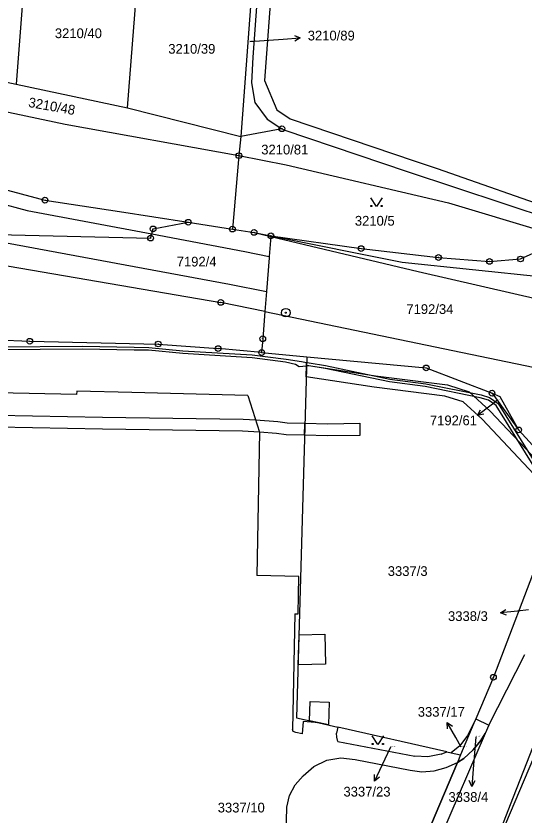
# Model space of a CAD drawing. Extents: x -593183 to -588034, y -1130415 to -1124994.
# Drawn here: x -592233 to -592144.3, y -1128273.9 to -1128134.3 of the extents above; entities that cross this region are included whole.
import ezdxf

# ---------------------------------------------------------------- set-up
doc = ezdxf.new("R2010")
doc.units = 0
for name, color, linetype in [('Vrstva 1', 7, 'Continuous'), ('Vrstva 16', 7, 'Continuous'), ('Vrstva 18', 7, 'Continuous'), ('Vrstva 24', 7, 'Continuous'), ('Vrstva 25', 7, 'Continuous'), ('Vrstva 27', 7, 'Continuous'), ('Vrstva 4', 7, 'Continuous')]:
    doc.layers.add(name, color=color, linetype=linetype)

msp = doc.modelspace()

# ---------------------------------------------------------------- linework, layer by layer
at = {"layer": 'Vrstva 1'}
for p, q in [((-592188.99, -1128105.22), (-592191.64, -1128141.44)), ((-592231.43, -1128125.97), (-592232.96, -1128146.18)), ((-592213.52, -1128150.28), (-592211.75, -1128127.62)), ((-592191.84, -1128129.32), (-592193.74, -1128155.31)), ((-592252.68, -1128142.07), (-592232.96, -1128146.18)), ((-592191.64, -1128141.44), (-592191.87, -1128145.92)), ((-592232.96, -1128146.18), (-592213.52, -1128150.28)), ((-592191.87, -1128145.92), (-592191.31, -1128149.37)), ((-592248.8, -1128148.01), (-592224.41, -1128153.13)), ((-592191.31, -1128149.37), (-592189.17, -1128152.26)), ((-592213.52, -1128150.28), (-592193.74, -1128155.31)), ((-592189.17, -1128152.26), (-592186.58, -1128153.95)), ((-592224.41, -1128153.13), (-592194.09, -1128158.65)), ((-592193.74, -1128155.31), (-592194.09, -1128158.65)), ((-592186.58, -1128153.95), (-592193.74, -1128155.31)), ((-592194.09, -1128158.65), (-592195.22, -1128171.47)), ((-592194.09, -1128158.65), (-592185.82, -1128160.27)), ((-592252.86, -1128159.79), (-592227.94, -1128166.42)), ((-592185.82, -1128160.27), (-592157.53, -1128166.89)), ((-592227.94, -1128166.42), (-592214.96, -1128168.42)), ((-592157.53, -1128166.89), (-592136.91, -1128173.09)), ((-592214.96, -1128168.42), (-592202.93, -1128170.28)), ((-592209.07, -1128171.45), (-592202.93, -1128170.28)), ((-592202.93, -1128170.28), (-592195.22, -1128171.47)), ((-592209.31, -1128172.32), (-592209.07, -1128171.45)), ((-592195.22, -1128171.47), (-592191.45, -1128172.05)), ((-592191.45, -1128172.05), (-592188.52, -1128172.64)), ((-592191.45, -1128172.05), (-592188.53, -1128172.75)), ((-592242.75, -1128172.26), (-592209.5, -1128173.04)), ((-592209.5, -1128173.04), (-592209.31, -1128172.32)), ((-592188.53, -1128172.75), (-592188.8, -1128176.25)), ((-592188.53, -1128172.75), (-592162.78, -1128178.89)), ((-592188.52, -1128172.64), (-592172.74, -1128174.88)), ((-592188.52, -1128172.64), (-592165.62, -1128177.22)), ((-592144.94, -1128176.69), (-592137.52, -1128173.33)), ((-592244.7, -1128176.17), (-592197.26, -1128184.27)), ((-592188.8, -1128176.25), (-592188.82, -1128176.49)), ((-592172.74, -1128174.88), (-592159.25, -1128176.43)), ((-592188.82, -1128176.49), (-592189.28, -1128182.39)), ((-592165.62, -1128177.22), (-592139.54, -1128179.94)), ((-592159.25, -1128176.43), (-592150.34, -1128177.12)), ((-592150.34, -1128177.12), (-592144.94, -1128176.69)), ((-592162.78, -1128178.89), (-592136.37, -1128184.95)), ((-592189.28, -1128182.39), (-592189.56, -1128185.87)), ((-592189.56, -1128185.87), (-592197.26, -1128184.27)), ((-592189.56, -1128185.87), (-592189.93, -1128190.61)), ((-592189.56, -1128185.87), (-592140.83, -1128195.96)), ((-592248.77, -1128190.28), (-592230.6, -1128191.05)), ((-592230.6, -1128191.05), (-592208.18, -1128191.53)), ((-592208.18, -1128191.53), (-592197.71, -1128192.32)), ((-592189.93, -1128190.61), (-592190.12, -1128193.03)), ((-592190.12, -1128193.03), (-592197.71, -1128192.32)), ((-592190.12, -1128193.03), (-592182.24, -1128193.77)), ((-592182.24, -1128193.77), (-592161.4, -1128195.71)), ((-592161.4, -1128195.71), (-592149.91, -1128200.11)), ((-592222.43, -1128200.36), (-592243.96, -1128199.91)), ((-592222.41, -1128199.76), (-592222.43, -1128200.36)), ((-592212.8, -1128200), (-592222.41, -1128199.76)), ((-592192.51, -1128200.51), (-592212.8, -1128200)), ((-592192.51, -1128200.51), (-592190.47, -1128206.93)), ((-592149.91, -1128200.11), (-592145.26, -1128206.52)), ((-592149.91, -1128200.11), (-592148.54, -1128200.68)), ((-592148.54, -1128200.68), (-592145.26, -1128206.52)), ((-592190.47, -1128206.93), (-592190.98, -1128231.93)), ((-592141.59, -1128210.59), (-592145.26, -1128206.52)), ((-592141.47, -1128228.18), (-592149.67, -1128249.69)), ((-592183.64, -1128232.11), (-592190.98, -1128231.93)), ((-592183.77, -1128238.65), (-592183.64, -1128232.11)), ((-592184.31, -1128238.64), (-592184.76, -1128258.83)), ((-592184.31, -1128238.64), (-592183.77, -1128238.65)), ((-592150.49, -1128258.09), (-592144.18, -1128245.72)), ((-592149.67, -1128249.69), (-592152.74, -1128256.96)), ((-592137.9, -1128249.31), (-592146.23, -1128270.62)), ((-592138.74, -1128254.44), (-592152.18, -1128286.25)), ((-592152.74, -1128256.96), (-592153.06, -1128257.71)), ((-592152.74, -1128256.96), (-592150.49, -1128258.09)), ((-592182.89, -1128257.44), (-592183.03, -1128259.56)), ((-592180.09, -1128257.67), (-592182.89, -1128257.44)), ((-592180.09, -1128257.67), (-592176.84, -1128258.4)), ((-592176.84, -1128258.4), (-592177.06, -1128259.46)), ((-592157.78, -1128262.71), (-592176.84, -1128258.4)), ((-592153.06, -1128257.71), (-592155.4, -1128263.25)), ((-592153.06, -1128257.71), (-592154.18, -1128259.89)), ((-592150.49, -1128258.09), (-592151.1, -1128259.5)), ((-592184.6, -1128259.17), (-592184.76, -1128258.83)), ((-592184.18, -1128259.34), (-592184.6, -1128259.17)), ((-592183.03, -1128259.56), (-592184.18, -1128259.34)), ((-592177, -1128260.16), (-592177.06, -1128259.46)), ((-592154.18, -1128259.89), (-592155.51, -1128261.69)), ((-592151.1, -1128259.5), (-592151.87, -1128260.74)), ((-592176.8, -1128260.91), (-592177, -1128260.16)), ((-592176.8, -1128260.91), (-592163.38, -1128263.5)), ((-592151.87, -1128260.74), (-592153.2, -1128262.38)), ((-592158.79, -1128263.12), (-592157.78, -1128262.71)), ((-592157.78, -1128262.71), (-592157.05, -1128262.88)), ((-592155.51, -1128261.69), (-592157.05, -1128262.88)), ((-592153.2, -1128262.38), (-592154.84, -1128263.86)), ((-592161.11, -1128263.6), (-592163.38, -1128263.5)), ((-592158.79, -1128263.12), (-592161.11, -1128263.6)), ((-592157.05, -1128262.88), (-592155.4, -1128263.25)), ((-592155.4, -1128263.25), (-592155.96, -1128264.56)), ((-592154.84, -1128263.86), (-592155.96, -1128264.56)), ((-592155.96, -1128264.56), (-592162.65, -1128280.4)), ((-592146.23, -1128270.62), (-592151.24, -1128283.43))]:
    msp.add_line(p, q, dxfattribs=at)
for points in [[(-592185.6, -1128090.36), (-592186.91, -1128108.64), (-592189.62, -1128145.54), (-592187.45, -1128150.66), (-592185.13, -1128152.24), (-592163.48, -1128159.55), (-592159.51, -1128160.9), (-592137.89, -1128168.47)], [(-592139.33, -1128169.87), (-592164.69, -1128161.47), (-592186.2, -1128154.2), (-592186.58, -1128153.95)], [(-592182.24, -1128193.77), (-592184.01, -1128256.78), (-592180.09, -1128257.67)]]:
    msp.add_lwpolyline(points, dxfattribs=at)
at = {"layer": 'Vrstva 16'}
for p, q in [((-592192.21, -1128138.72), (-592186.36, -1128138.3)), ((-592148.93, -1128201.32), (-592150.05, -1128202.18)), ((-592143.53, -1128237.93), (-592145.45, -1128238.14)), ((-592155.28, -1128261.88), (-592156.23, -1128260.21)), ((-592152.74, -1128260.07), (-592153.21, -1128265.75)), ((-592167.65, -1128261.88), (-592169.14, -1128265.09))]:
    msp.add_line(p, q, dxfattribs=at)
at = {"layer": 'Vrstva 24'}
for centre, radius in [((-592186.58, -1128153.95), 0.5), ((-592186.58, -1128153.95), 0.0327), ((-592194.09, -1128158.65), 0.5), ((-592194.09, -1128158.65), 0.0327), ((-592227.94, -1128166.42), 0.5), ((-592227.94, -1128166.42), 0.0327), ((-592202.93, -1128170.28), 0.5), ((-592202.93, -1128170.28), 0.0327), ((-592209.07, -1128171.45), 0.5), ((-592209.07, -1128171.45), 0.0327), ((-592195.22, -1128171.47), 0.5), ((-592195.22, -1128171.47), 0.0327), ((-592191.45, -1128172.05), 0.5), ((-592191.45, -1128172.05), 0.0327), ((-592209.5, -1128173.04), 0.5), ((-592209.5, -1128173.04), 0.0327), ((-592188.52, -1128172.64), 0.5), ((-592188.52, -1128172.64), 0.0327), ((-592172.74, -1128174.88), 0.5), ((-592172.74, -1128174.88), 0.0327), ((-592159.25, -1128176.43), 0.5), ((-592144.94, -1128176.69), 0.5), ((-592159.25, -1128176.43), 0.0327), ((-592150.34, -1128177.12), 0.5), ((-592150.34, -1128177.12), 0.0327), ((-592144.94, -1128176.69), 0.0327), ((-592197.26, -1128184.27), 0.5), ((-592197.26, -1128184.27), 0.0327), ((-592185.92, -1128186.06), 0.75), ((-592185.92, -1128186.06), 0.0903), ((-592189.93, -1128190.61), 0.5), ((-592230.6, -1128191.05), 0.5), ((-592230.6, -1128191.05), 0.0327), ((-592208.18, -1128191.53), 0.5), ((-592208.18, -1128191.53), 0.0327), ((-592189.93, -1128190.61), 0.0327), ((-592197.71, -1128192.32), 0.5), ((-592197.71, -1128192.32), 0.0327), ((-592190.12, -1128193.03), 0.5), ((-592190.12, -1128193.03), 0.0327), ((-592161.4, -1128195.71), 0.5), ((-592161.4, -1128195.71), 0.0327), ((-592149.91, -1128200.11), 0.5), ((-592149.91, -1128200.11), 0.0327), ((-592145.26, -1128206.52), 0.5), ((-592145.26, -1128206.52), 0.0327), ((-592149.67, -1128249.69), 0.5), ((-592149.67, -1128249.69), 0.0327)]:
    msp.add_circle(centre, radius, dxfattribs=at)
at = {"layer": 'Vrstva 25'}
for p, q in [((-592186.36, -1128138.3), (-592183.37, -1128138.08)), ((-592150.05, -1128202.18), (-592152.43, -1128204.01)), ((-592145.45, -1128238.14), (-592148.43, -1128238.47)), ((-592156.23, -1128260.21), (-592157.71, -1128257.6)), ((-592169.14, -1128265.09), (-592170.4, -1128267.81)), ((-592153.21, -1128265.75), (-592153.46, -1128268.74))]:
    msp.add_line(p, q, dxfattribs=at)
for points in [[(-592184.4, -1128137.66), (-592183.37, -1128138.08), (-592184.33, -1128138.65)], [(-592169.08, -1128166.03), (-592170.08, -1128167.53), (-592171.08, -1128166.03)], [(-592151.33, -1128203.8), (-592152.43, -1128204.01), (-592151.94, -1128203)], [(-592147.38, -1128238.85), (-592148.43, -1128238.47), (-592147.49, -1128237.86)], [(-592157.65, -1128258.72), (-592157.71, -1128257.6), (-592156.78, -1128258.22)], [(-592168.85, -1128259.95), (-592169.85, -1128261.45), (-592170.85, -1128259.95)], [(-592169.53, -1128267.11), (-592170.4, -1128267.81), (-592170.43, -1128266.69)], [(-592152.88, -1128267.78), (-592153.46, -1128268.74), (-592153.87, -1128267.7)]]:
    msp.add_lwpolyline(points, dxfattribs=at)
for centre in [(-592170.98, -1128167.43), (-592169.18, -1128167.43), (-592170.75, -1128261.35), (-592168.95, -1128261.35)]:
    msp.add_circle(centre, 0.1, dxfattribs=at)
at = {"layer": 'Vrstva 27'}
for p, q in [((-592246.64, -1128192.12), (-592221.4, -1128191.93)), ((-592221.4, -1128192.43), (-592246.62, -1128192.62)), ((-592221.4, -1128191.93), (-592212.36, -1128192.09)), ((-592212.38, -1128192.59), (-592221.4, -1128192.43)), ((-592209.87, -1128192.63), (-592212.38, -1128192.59)), ((-592212.36, -1128192.09), (-592209.83, -1128192.13)), ((-592203.89, -1128193.2), (-592209.87, -1128192.63)), ((-592209.83, -1128192.13), (-592203.87, -1128192.7)), ((-592203.87, -1128192.7), (-592191.75, -1128193.44)), ((-592191.79, -1128193.94), (-592203.89, -1128193.2)), ((-592185.97, -1128194.69), (-592191.79, -1128193.94)), ((-592191.75, -1128193.44), (-592185.85, -1128194.2)), ((-592185.85, -1128194.2), (-592183.16, -1128194.56)), ((-592184.19, -1128195.12), (-592185.97, -1128194.69)), ((-592183.6, -1128195.53), (-592184.19, -1128195.12)), ((-592182.29, -1128195.38), (-592183.6, -1128195.53)), ((-592183.16, -1128194.56), (-592182.27, -1128194.75)), ((-592182.34, -1128197.27), (-592182.28, -1128195.25)), ((-592182.29, -1128195.38), (-592182.27, -1128194.75)), ((-592182.27, -1128194.75), (-592182.29, -1128195.38)), ((-592181.91, -1128195.33), (-592182.29, -1128195.38)), ((-592182.28, -1128195.25), (-592170.22, -1128197.07)), ((-592182.27, -1128194.75), (-592181.85, -1128194.84)), ((-592179.05, -1128195.79), (-592181.91, -1128195.33)), ((-592181.85, -1128194.84), (-592178.95, -1128195.3)), ((-592167.82, -1128198.15), (-592179.05, -1128195.79)), ((-592178.95, -1128195.3), (-592167.73, -1128197.65)), ((-592170.22, -1128197.07), (-592157.68, -1128198.66)), ((-592170.5, -1128199.05), (-592182.34, -1128197.27)), ((-592161.55, -1128198.97), (-592167.82, -1128198.15)), ((-592167.73, -1128197.65), (-592161.47, -1128198.47)), ((-592161.47, -1128198.47), (-592151.81, -1128200.43)), ((-592158.12, -1128200.62), (-592170.5, -1128199.05)), ((-592151.95, -1128200.91), (-592161.55, -1128198.97)), ((-592157.68, -1128198.66), (-592153.91, -1128199.86)), ((-592153.91, -1128199.86), (-592150.22, -1128203.23)), ((-592154.93, -1128201.64), (-592158.12, -1128200.62)), ((-592150.55, -1128201.35), (-592151.95, -1128200.91)), ((-592151.81, -1128200.43), (-592150.33, -1128200.89)), ((-592149.19, -1128202.29), (-592150.55, -1128201.35)), ((-592150.33, -1128200.89), (-592148.83, -1128201.93)), ((-592151.62, -1128204.65), (-592154.93, -1128201.64)), ((-592142.25, -1128213.44), (-592149.19, -1128202.29)), ((-592148.83, -1128201.93), (-592142.15, -1128212.67)), ((-592242.3, -1128203.8), (-592217.88, -1128204.3)), ((-592150.22, -1128203.23), (-592140.42, -1128213.65)), ((-592217.88, -1128204.3), (-592193.37, -1128204.62)), ((-592193.37, -1128204.62), (-592191.16, -1128204.77)), ((-592191.16, -1128204.77), (-592187.28, -1128205.04)), ((-592187.28, -1128205.04), (-592185.67, -1128205.26)), ((-592185.67, -1128205.26), (-592182.56, -1128205.34)), ((-592182.56, -1128205.34), (-592182.62, -1128207.44)), ((-592182.62, -1128207.44), (-592182.56, -1128205.34)), ((-592182.56, -1128205.34), (-592178.58, -1128205.44)), ((-592178.58, -1128205.44), (-592173, -1128205.37)), ((-592173, -1128205.37), (-592172.97, -1128207.48)), ((-592142.62, -1128214.23), (-592151.62, -1128204.65)), ((-592217.92, -1128206.41), (-592242.34, -1128205.91)), ((-592193.45, -1128206.73), (-592217.92, -1128206.41)), ((-592190.47, -1128206.93), (-592193.45, -1128206.73)), ((-592187.5, -1128207.14), (-592190.47, -1128206.93)), ((-592185.83, -1128207.36), (-592187.5, -1128207.14)), ((-592182.62, -1128207.44), (-592185.83, -1128207.36)), ((-592178.6, -1128207.55), (-592182.62, -1128207.44)), ((-592172.97, -1128207.48), (-592178.6, -1128207.55)), ((-592183.75, -1128247.53), (-592183.6, -1128242.27)), ((-592183.6, -1128242.27), (-592179.08, -1128242.16)), ((-592179.08, -1128242.16), (-592178.95, -1128247.41)), ((-592178.95, -1128247.41), (-592183.75, -1128247.53)), ((-592181.75, -1128257.29), (-592181.63, -1128253.94)), ((-592181.63, -1128253.94), (-592178.33, -1128254.06)), ((-592178.33, -1128254.06), (-592178.48, -1128258.03)), ((-592180.09, -1128257.67), (-592181.75, -1128257.29)), ((-592178.48, -1128258.03), (-592180.09, -1128257.67)), ((-592151.1, -1128259.5), (-592162.55, -1128286.12)), ((-592151.87, -1128260.74), (-592151.1, -1128259.5)), ((-592153.2, -1128262.38), (-592151.87, -1128260.74)), ((-592154.84, -1128263.86), (-592153.2, -1128262.38)), ((-592180.99, -1128265.26), (-592178.73, -1128264.19)), ((-592178.73, -1128264.19), (-592176.27, -1128263.76)), ((-592176.27, -1128263.76), (-592173.79, -1128264.08)), ((-592173.79, -1128264.08), (-592164.17, -1128265.91)), ((-592155.96, -1128264.56), (-592154.84, -1128263.86)), ((-592182.85, -1128266.88), (-592180.99, -1128265.26)), ((-592155.96, -1128264.56), (-592162.65, -1128280.4)), ((-592162.65, -1128280.4), (-592155.96, -1128264.56)), ((-592160.02, -1128266.01), (-592157.92, -1128265.47)), ((-592157.92, -1128265.47), (-592155.96, -1128264.56)), ((-592184.27, -1128268.45), (-592182.85, -1128266.88)), ((-592164.17, -1128265.91), (-592162.17, -1128266.18)), ((-592162.17, -1128266.18), (-592160.02, -1128266.01)), ((-592185.25, -1128270.33), (-592184.27, -1128268.45)), ((-592185.73, -1128272.39), (-592185.25, -1128270.33)), ((-592186.37, -1128305.64), (-592185.73, -1128272.39))]:
    msp.add_line(p, q, dxfattribs=at)
at = {"layer": 'Vrstva 4'}
for p, q in [((-592251.38, -1128162.75), (-592231.05, -1128168.23)), ((-592231.05, -1128168.23), (-592209.31, -1128172.32)), ((-592239.33, -1128173.04), (-592195.73, -1128181.06)), ((-592209.31, -1128172.32), (-592193.04, -1128175.38)), ((-592188.52, -1128172.64), (-592188.53, -1128172.75)), ((-592193.04, -1128175.38), (-592188.8, -1128176.25)), ((-592195.73, -1128181.06), (-592189.28, -1128182.39))]:
    msp.add_line(p, q, dxfattribs=at)

# ---------------------------------------------------------------- texts
at = {"layer": 'Vrstva 16'}
for s, p in [('3210/89', (-592182.08, -1128138.54)), ('7192/61', (-592160.75, -1128205.71)), ('3338/3', (-592157.59, -1128239.88)), ('3337/17', (-592162.87, -1128256.59)), ('3337/23', (-592175.84, -1128270.52)), ('3338/4', (-592157.51, -1128271.45))]:
    msp.add_text(s, height=1.7, dxfattribs=at).set_placement(p)
at = {"layer": 'Vrstva 18'}
for s, height, p in [('3210/40', 1.7, (-592226.22, -1128138.14)), ('3210/89', 0.2, (-592192.21, -1128138.72)), ('3210/39', 1.7, (-592206.42, -1128140.86)), ('3210/81', 1.7, (-592190.19, -1128158.44)), ('3210/5', 1.7, (-592173.85, -1128170.87)), ('7192/4', 1.7, (-592204.95, -1128178)), ('7192/34', 1.7, (-592164.86, -1128186.29)), ('7192/61', 0.1, (-592148.93, -1128201.32)), ('3337/3', 1.7, (-592168.11, -1128232.02)), ('3338/4', 0.2, (-592152.74, -1128260.07)), ('3337/23', 0.2, (-592167.65, -1128261.88)), ('3337/17', 0.2, (-592155.28, -1128261.88)), ('3337/10', 1.7, (-592197.79, -1128273.3))]:
    msp.add_text(s, height=height, dxfattribs=at).set_placement(p)
msp.add_text('3210/48', height=1.7, rotation=349.928, dxfattribs=at).set_placement((-592230.93, -1128150.13))

doc.saveas('drawing.dxf')
